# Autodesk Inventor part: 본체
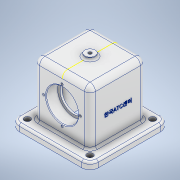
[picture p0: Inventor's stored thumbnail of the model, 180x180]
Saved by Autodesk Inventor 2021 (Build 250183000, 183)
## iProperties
Created: 2022-07
Part Number: 본체
Material: 알루미늄 6061
Document SubType Name: Modeling
Designer: i
Mass: 1058.33 g
Surface Area: 726.505 cm^2
Volume: 391.974 cm^3
Density: 2.7 g/cm^3
Appearance: 알루미늄 - 평지
Author: i
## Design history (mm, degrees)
sketch "스케치1"
  geometry: 1 further point
sketch "스케치2"
  geometry: L1 (58, -58)-(-58, -58); L2 (-58, -58)-(-58, 58); L3 (-58, 58)-(58, 58); L4 (58, 58)-(58, -58); L5 (58, -58)-(-58, 58); L6 (-58, -58)-(58, 58); 1 further point
  constraints: 12 end point, 2 midpoint, 2 parallel, 1 horizontal, 1 perpendicular
  dimensions: "d0" = 116 distance of L1.start L1.end; "d1" = 116 distance of L1.end L2.end
extrude "돌출1" new body sketch "스케치2" distance "d2" = 10; taper "d3" = 0 deg
sketch "스케치3"
  geometry: L1 (-41, 41)-(41, 41); L2 (41, 41)-(41, -41); L3 (41, -41)-(-41, -41); L4 (-41, -41)-(-41, 41); L5 (-41, 41)-(41, -41); L6 (41, 41)-(-41, -41); 1 further point
  constraints: 12 end point, 2 midpoint, 2 parallel, 1 horizontal, 1 perpendicular
  dimensions: "d4" = 82 distance of L1.start L1.end; "d5" = 82 distance of L1.end L2.end
extrude "돌출2" join sketch "스케치3" distance "d6" = 80; taper "d7" = 0 deg
node "작업 평면1"
sketch "스케치5"
  geometry: C1 r 7.5 at (0, 0); 1 further point
  constraints: 1 centre point, 1 coincident
  dimensions: "d9" = 15 diameter of C1
extrude "돌출3" join sketch "스케치5" stored distance "d10" = 80; taper "d11" = 0 deg
sketch "스케치7"
  geometry: L1 (-17, -10)-(99, -10) reference; C1 r 23.5 at (41, 38); 2 further points
  constraints: 1 centre point, 1 midpoint, 1 vertical alignment
  dimensions: "d12" = 47 diameter of C1; "d13" = 48 distance from line of L1 C1.centre
extrude "돌출4" cut sketch "스케치7" distance "d14" = 17; taper "d15" = 0 deg
sketch "스케치8"
  geometry: C1 r 23.5 at (0, 0) reference; C2 r 20 at (0, 0); 1 further point
  constraints: 1 centre point, 1 coincident
  dimensions: "d16" = 40 diameter of C2
extrude "돌출5" cut sketch "스케치8" stored distance "d17" = 0; taper "d18" = 0 deg
sketch "스케치9"
  geometry: C1 r 20 at (41, 38) reference; C2 r 20 at (41, 38) reference; C3 r 23.5 at (41, 38); 1 further point
  constraints: 1 centre point, 1 coincident
  dimensions: "d19" = 47 diameter of C3
extrude "돌출6" cut sketch "스케치9" distance "d20" = 17; taper "d21" = 0 deg
sketch "스케치10" dims "d22" = 54
  geometry: L1 (41, 38)-(41, 65); C1 r 23.5 at (41, 38) reference; 2 further points
  constraints: 2 coincident, 2 end point, 1 vertical, 1 vertical alignment, 2 other
hole "구멍1" sketch "스케치10" at (41, 65) diameter "d23" = 3.242; stored, may be unused: countersink angle "d27" = 90 deg, drill point angle "d29" = 118 deg; dims "d24" = 8, "d25" = 4, "d26" = 2, "d28" = 10
sketch "스케치11"
  geometry: C1 r 7.5 at (0, 0) reference; 2 further points
  constraints: 1 coincident
hole "구멍2" sketch "스케치11" at (0, 0) diameter "d33" = 4.917; stored, may be unused: countersink angle "d37" = 90 deg, drill point angle "d39" = 0 deg; dims "d34" = 10, "d35" = 4, "d36" = 2, "d38" = 10
fillet "모깎기1" dims "d40" = 8
fillet "모깎기2" dims "d41" = 12
sketch "스케치13"
  geometry: A1 r 12 centre (-46, 46) between (-46, 58) and (-58, 46) reference; A2 r 12 centre (46, 46) between (58, 46) and (46, 58) reference; A3 r 12 centre (46, -46) between (46, -58) and (58, -46) reference; A4 r 12 centre (-46, -46) between (-58, -46) and (-46, -58) reference; 5 further points
  constraints: 4 coincident
hole "구멍3" sketch "스케치13" at (-46, 46), (46, 46), (46, -46), (-46, -46) diameter "d42" = 9; stored, may be unused: countersink angle "d46" = 90 deg, drill point angle "d48" = 0 deg; dims "d43" = 12, "d44" = 4, "d45" = 2, "d47" = 30
chamfer "모따기1" distance "d49" = 1; stored, may be unused: second distance "d50" = 2, angle "d51" = 45 deg
fillet "모깎기3" dims "d52" = 3
sketch "스케치14"
  geometry: L1 (90, 33)-(90, -33) reference; L2 (0, -46)-(0, 46) reference; A1 r 8 centre (82, 33) between (90, 33) and (82, 41) reference; A2 r 8 centre (82, -33) between (82, -41) and (90, -33) reference; 1 further point
sketch "스케치15"
  geometry: L1 (30, 21)-(-30, 21); L2 (-30, 21)-(-30, -21); L3 (-30, -21)-(30, -21); L4 (30, -21)-(30, 21); L5 (30, 21)-(-30, -21); L6 (-30, 21)-(30, -21); L7 (-33, -33)-(33, -33) reference; 2 further points
  constraints: 12 end point, 2 midpoint, 2 parallel, 1 horizontal, 1 perpendicular
  dimensions: "d53" = 42 distance of L3.end L1.start; "d55" = 60 distance of L2.end L3.end
extrude "돌출7" cut sketch "스케치15" distance "d56" = 80; taper "d57" = 0 deg
fillet "모깎기4" dims "d58" = 3
sketch "스케치16"
  geometry: L1 (-13, -82)-(79, -82) reference; 3 further points
  constraints: 1 midpoint, 1 vertical alignment, 1 other
  dimensions: "d59" = 45 distance from line of L1 point (33, -37)
feature "엠보싱1" sketch "스케치16" dims "d0" = 116, "d1" = 116, "d60" = 0.5, "d61" = 0
node "솔리드1"
pattern_circular "원형 패턴1" dims angle "d31" = 360 deg
mirror "미러1"
feature "A9D066F2-1C7D-4E18-AEED-F7BC21143FA4" dims "d33" = 4.917, "d34" = 10, "d35" = 4, "d36" = 2, "d37" = 90 deg, "d38" = 10, "d39" = 0
other parameters: "d8" = 4
